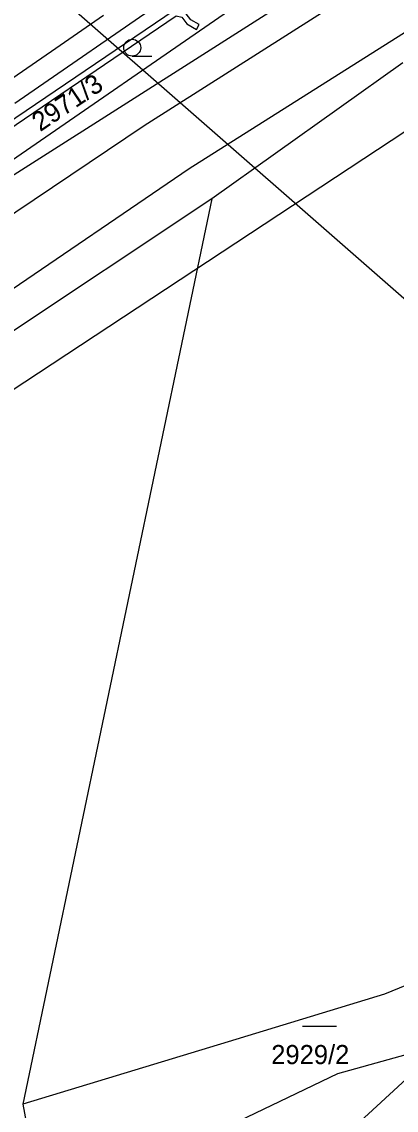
# Model space of a CAD drawing. Extents: x -620552 to -620056, y -1123312 to -1122890.
# Drawn here: x -620235.1 to -620201.8, y -1123045.1 to -1122948.3 of the extents above; entities that cross this region are included whole.
import ezdxf

# ---------------------------------------------------------------- set-up
doc = ezdxf.new("R2010")
doc.units = 0
for name, color, linetype in [('CETIN', 7, 'Continuous'), ('HranDP', 7, 'Continuous'), ('Hranice parcel', 7, 'Continuous'), ('Parcelní čísla', 7, 'Continuous'), ('Rámečky', 7, 'Continuous'), ('Rámečky-tisk', 7, 'Continuous'), ('VAS vodovod', 7, 'Continuous'), ('Vnitřní kresba', 7, 'Continuous'), ('Věcná břemena k části', 7, 'Continuous'), ('Značky kultur', 7, 'Continuous')]:
    doc.layers.add(name, color=color, linetype=linetype)

msp = doc.modelspace()

# ---------------------------------------------------------------- linework, layer by layer
at = {"layer": 'CETIN'}
for points in [[(-620249.32, -1122970.47), (-620218.63, -1122950.99), (-620187.55, -1122931.18), (-620162.84, -1122907.83)], [(-620523.507, -1123111.553), (-620453.589, -1123102.463), (-620423.237, -1123094.915), (-620404.669, -1123086.509), (-620368.955, -1123067.056), (-620277.606, -1123008.491), (-620145.621, -1122921.549)]]:
    msp.add_lwpolyline(points, dxfattribs=at)
at = {"layer": 'HranDP'}
msp.add_lwpolyline([(-620197.49, -1123039.27), (-620212.08, -1123052.71), (-620231.41, -1123063.68)], dxfattribs=at)
at = {"layer": 'Hranice parcel'}
for p, q in [((-620251.74, -1122971.48), (-620208, -1122941.31)), ((-620221.39, -1122945.68), (-620235.69, -1122955.55)), ((-620201.16, -1122951.94), (-620218.17, -1122964.05)), ((-620218.17, -1122964.05), (-620242.46, -1122980.18)), ((-620218.17, -1122964.05), (-620234.98, -1123044.6)), ((-620234.98, -1123044.6), (-620234.38, -1123047.81))]:
    msp.add_line(p, q, dxfattribs=at)
for points in [[(-620194.62, -1123031.45), (-620202.81, -1123034.81), (-620216.72, -1123039.04), (-620234.98, -1123044.6)], [(-620197.49, -1123039.27), (-620207, -1123041.9), (-620218.72, -1123047.54), (-620234.38, -1123047.81)], [(-620197.49, -1123039.27), (-620212.08, -1123052.71), (-620231.41, -1123063.68)]]:
    msp.add_lwpolyline(points, dxfattribs=at)
at = {"layer": 'Rámečky'}
msp.add_lwpolyline([(-620255.57, -1122925.224), (-620158.492, -1123010.143), (-620126.701, -1122973.8)], dxfattribs=at)
at = {"layer": 'Rámečky-tisk'}
msp.add_lwpolyline([(-620255.57, -1122925.224), (-620158.492, -1123010.143), (-620126.701, -1122973.8)], dxfattribs=at)
at = {"layer": 'VAS vodovod'}
msp.add_lwpolyline([(-620227.81, -1122947.715), (-620232.06, -1122950.65), (-620238.495, -1122955.085)], dxfattribs=at)
at = {"layer": 'Vnitřní kresba'}
for p, q in [((-620149.743, -1122910.169), (-620224.19, -1122957.54)), ((-620147.785, -1122915.574), (-620220.18, -1122961.38)), ((-620224.19, -1122957.54), (-620283.1, -1122997.08)), ((-620220.18, -1122961.38), (-620275.49, -1122998.97))]:
    msp.add_line(p, q, dxfattribs=at)
at = {"layer": 'Věcná břemena k části'}
msp.add_lwpolyline([(-620238.02, -1122959.05), (-620221.34, -1122947.77), (-620220.85, -1122947.88), (-620220.38, -1122948.48), (-620219.54, -1122948.96), (-620219.3, -1122948.52), (-620220.04, -1122948.1), (-620220.45, -1122947.58), (-620220.43, -1122947.18), (-620215.58, -1122944.45), (-620213.67, -1122944.01), (-620209.12, -1122941.46), (-620208.72, -1122940.34), (-620210.39, -1122938.08), (-620210.8, -1122938.37), (-620209.28, -1122940.42), (-620209.52, -1122941.12), (-620213.85, -1122943.53), (-620215.76, -1122943.97), (-620220.91, -1122946.88), (-620220.94, -1122947.35), (-620221.44, -1122947.23), (-620238.3, -1122958.63)], dxfattribs=at)
at = {"layer": 'Značky kultur'}
for p, q in [((-620225.253, -1122951.34), (-620223.503, -1122951.34)), ((-620210.088, -1123037.67), (-620207.088, -1123037.67))]:
    msp.add_line(p, q, dxfattribs=at)
msp.add_circle((-620225.253, -1122950.59), 0.75, dxfattribs=at)

# ---------------------------------------------------------------- texts
at = {"layer": 'Parcelní čísla'}
msp.add_text('2971/3', height=1.7, rotation=34, dxfattribs=at).set_placement((-620233.448, -1122958.113))
msp.add_text('2929/2', height=1.7, dxfattribs=at).set_placement((-620212.885, -1123041.036))

doc.saveas('drawing.dxf')
